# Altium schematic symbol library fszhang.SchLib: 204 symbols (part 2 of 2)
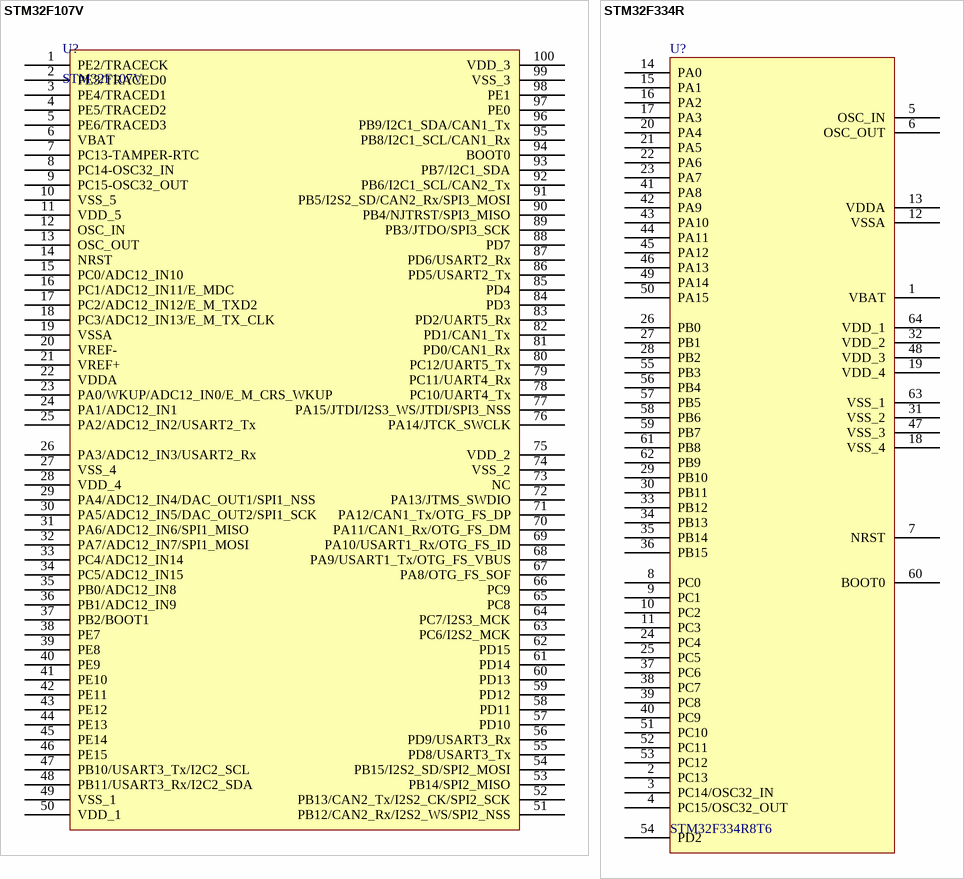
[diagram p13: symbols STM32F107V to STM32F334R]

## STM32F107V
designator U?
STM32单片机100引脚
footprint LQFP-100_M (Thin QFP, 100)
pins: 1 PE2/TRACECK, 2 PE3/TRACED0, 3 PE4/TRACED1, 4 PE5/TRACED2, 5 PE6/TRACED3, 6 VBAT, 7 PC13-TAMPER-RTC, 8 PC14-OSC32_IN, 9 PC15-OSC32_OUT, 10 VSS_5, 11 VDD_5, 12 OSC_IN, 13 OSC_OUT, 14 NRST, 15 PC0/ADC12_IN10, 16 PC1/ADC12_IN11/E_MDC, 17 PC2/ADC12_IN12/E_M_TXD2, 18 PC3/ADC12_IN13/E_M_TX_CLK, 19 VSSA, 20 VREF-, 21 VREF+, 22 VDDA, 23 PA0/WKUP/ADC12_IN0/E_M_CRS_WKUP, 24 PA1/ADC12_IN1, 25 PA2/ADC12_IN2/USART2_Tx, 26 PA3/ADC12_IN3/USART2_Rx, 27 VSS_4, 28 VDD_4, 29 PA4/ADC12_IN4/DAC_OUT1/SPI1_NSS, 30 PA5/ADC12_IN5/DAC_OUT2/SPI1_SCK, 31 PA6/ADC12_IN6/SPI1_MISO, 32 PA7/ADC12_IN7/SPI1_MOSI, 33 PC4/ADC12_IN14, 34 PC5/ADC12_IN15, 35 PB0/ADC12_IN8, 36 PB1/ADC12_IN9, 37 PB2/BOOT1, 38 PE7, 39 PE8, 40 PE9, 41 PE10, 42 PE11, 43 PE12, 44 PE13, 45 PE14, 46 PE15, 47 PB10/USART3_Tx/I2C2_SCL, 48 PB11/USART3_Rx/I2C2_SDA, 49 VSS_1, 50 VDD_1, 51 PB12/CAN2_Rx/I2S2_WS/SPI2_NSS, 52 PB13/CAN2_Tx/I2S2_CK/SPI2_SCK, 53 PB14/SPI2_MISO, 54 PB15/I2S2_SD/SPI2_MOSI, 55 PD8/USART3_Tx, 56 PD9/USART3_Rx, 57 PD10, 58 PD11, 59 PD12, 60 PD13, 61 PD14, 62 PD15, 63 PC6/I2S2_MCK, 64 PC7/I2S3_MCK, 65 PC8, 66 PC9, 67 PA8/OTG_FS_SOF, 68 PA9/USART1_Tx/OTG_FS_VBUS, 69 PA10/USART1_Rx/OTG_FS_ID, 70 PA11/CAN1_Rx/OTG_FS_DM, 71 PA12/CAN1_Tx/OTG_FS_DP, 72 PA13/JTMS_SWDIO, 73 NC, 74 VSS_2, 75 VDD_2, 76 PA14/JTCK_SWCLK, 77 PA15/JTDI/I2S3_WS/JTDI/SPI3_NSS, 78 PC10/UART4_Tx, 79 PC11/UART4_Rx, 80 PC12/UART5_Tx, 81 PD0/CAN1_Rx, 82 PD1/CAN1_Tx, 83 PD2/UART5_Rx, 84 PD3, 85 PD4, 86 PD5/USART2_Tx, 87 PD6/USART2_Rx, 88 PD7, 89 PB3/JTDO/SPI3_SCK, 90 PB4/NJTRST/SPI3_MISO, 91 PB5/I2S2_SD/CAN2_Rx/SPI3_MOSI, 92 PB6/I2C1_SCL/CAN2_Tx, 93 PB7/I2C1_SDA, 94 BOOT0, 95 PB8/I2C1_SCL/CAN1_Rx, 96 PB9/I2C1_SDA/CAN1_Tx, 97 PE0, 98 PE1, 99 VSS_3, 100 VDD_3

## STM32F334R
designator U?, comment STM32F334R8T6
STM32单片机64引脚
footprint LQFP-64_EP (LQFP64)
footprint LQFP-64 (LQFP64)
pins: 1 VBAT, 2 PC13, 3 PC14/OSC32_IN, 4 PC15/OSC32_OUT, 5 OSC_IN, 6 OSC_OUT, 7 NRST, 8 PC0, 9 PC1, 10 PC2, 11 PC3, 12 VSSA, 13 VDDA, 14 PA0, 15 PA1, 16 PA2, 17 PA3, 18 VSS_4, 19 VDD_4, 20 PA4, 21 PA5, 22 PA6, 23 PA7, 24 PC4, 25 PC5, 26 PB0, 27 PB1, 28 PB2, 29 PB10, 30 PB11, 31 VSS_2, 32 VDD_2, 33 PB12, 34 PB13, 35 PB14, 36 PB15, 37 PC6, 38 PC7, 39 PC8, 40 PC9, 41 PA8, 42 PA9, 43 PA10, 44 PA11, 45 PA12, 46 PA13, 47 VSS_3, 48 VDD_3, 49 PA14, 50 PA15, 51 PC10, 52 PC11, 53 PC12, 54 PD2, 55 PB3, 56 PB4, 57 PB5, 58 PB6, 59 PB7, 60 BOOT0, 61 PB8, 62 PB9, 63 VSS_1, 64 VDD_1

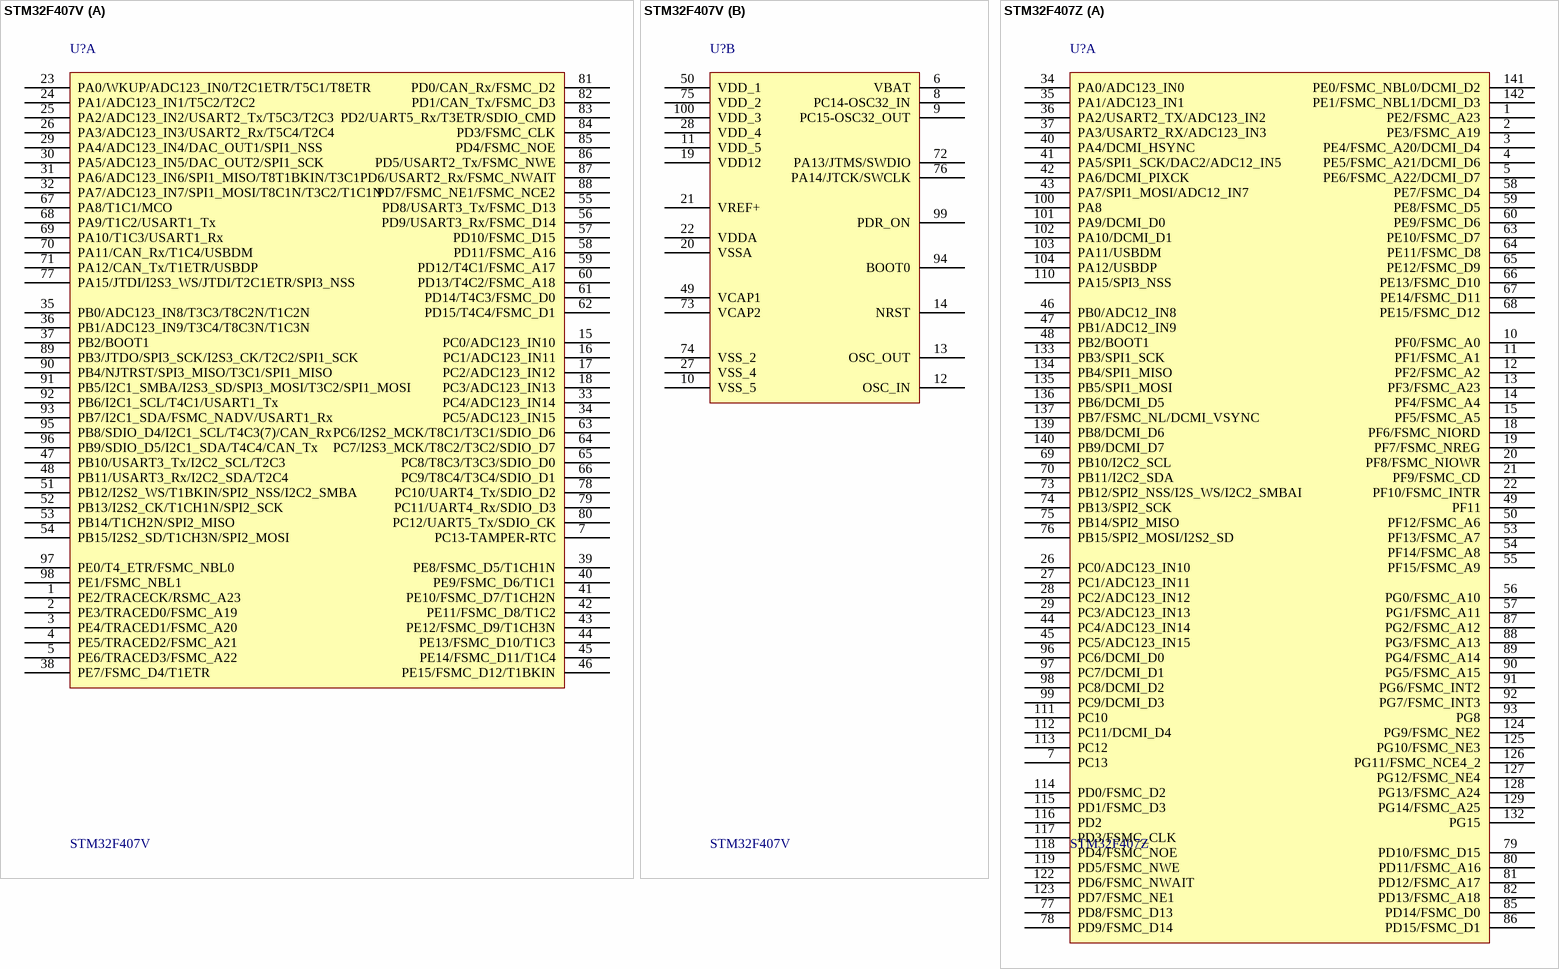
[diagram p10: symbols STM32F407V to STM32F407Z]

## STM32F407V
designator U?
STM32单片机100引脚
footprint LQFP-100_M (Thin QFP, 100)
part A pins: 1 PE2/TRACECK/RSMC_A23, 2 PE3/TRACED0/FSMC_A19, 3 PE4/TRACED1/FSMC_A20, 4 PE5/TRACED2/FSMC_A21, 5 PE6/TRACED3/FSMC_A22, 7 PC13-TAMPER-RTC, 15 PC0/ADC123_IN10, 16 PC1/ADC123_IN11, 17 PC2/ADC123_IN12, 18 PC3/ADC123_IN13, 23 PA0/WKUP/ADC123_IN0/T2C1ETR/T5C1/T8ETR, 24 PA1/ADC123_IN1/T5C2/T2C2, 25 PA2/ADC123_IN2/USART2_Tx/T5C3/T2C3, 26 PA3/ADC123_IN3/USART2_Rx/T5C4/T2C4, 29 PA4/ADC123_IN4/DAC_OUT1/SPI1_NSS, 30 PA5/ADC123_IN5/DAC_OUT2/SPI1_SCK, 31 PA6/ADC123_IN6/SPI1_MISO/T8T1BKIN/T3C1, 32 PA7/ADC123_IN7/SPI1_MOSI/T8C1N/T3C2/T1C1N, 33 PC4/ADC123_IN14, 34 PC5/ADC123_IN15, 35 PB0/ADC123_IN8/T3C3/T8C2N/T1C2N, 36 PB1/ADC123_IN9/T3C4/T8C3N/T1C3N, 37 PB2/BOOT1, 38 PE7/FSMC_D4/T1ETR, 39 PE8/FSMC_D5/T1CH1N, 40 PE9/FSMC_D6/T1C1, 41 PE10/FSMC_D7/T1CH2N, 42 PE11/FSMC_D8/T1C2, 43 PE12/FSMC_D9/T1CH3N, 44 PE13/FSMC_D10/T1C3, 45 PE14/FSMC_D11/T1C4, 46 PE15/FSMC_D12/T1BKIN, 47 PB10/USART3_Tx/I2C2_SCL/T2C3, 48 PB11/USART3_Rx/I2C2_SDA/T2C4, 51 PB12/I2S2_WS/T1BKIN/SPI2_NSS/I2C2_SMBA, 52 PB13/I2S2_CK/T1CH1N/SPI2_SCK, 53 PB14/T1CH2N/SPI2_MISO, 54 PB15/I2S2_SD/T1CH3N/SPI2_MOSI, 55 PD8/USART3_Tx/FSMC_D13, 56 PD9/USART3_Rx/FSMC_D14, 57 PD10/FSMC_D15, 58 PD11/FSMC_A16, 59 PD12/T4C1/FSMC_A17, 60 PD13/T4C2/FSMC_A18, 61 PD14/T4C3/FSMC_D0, 62 PD15/T4C4/FSMC_D1, 63 PC6/I2S2_MCK/T8C1/T3C1/SDIO_D6, 64 PC7/I2S3_MCK/T8C2/T3C2/SDIO_D7, 65 PC8/T8C3/T3C3/SDIO_D0, 66 PC9/T8C4/T3C4/SDIO_D1, 67 PA8/T1C1/MCO, 68 PA9/T1C2/USART1_Tx, 69 PA10/T1C3/USART1_Rx, 70 PA11/CAN_Rx/T1C4/USBDM, 71 PA12/CAN_Tx/T1ETR/USBDP, 77 PA15/JTDI/I2S3_WS/JTDI/T2C1ETR/SPI3_NSS, 78 PC10/UART4_Tx/SDIO_D2, 79 PC11/UART4_Rx/SDIO_D3, 80 PC12/UART5_Tx/SDIO_CK, 81 PD0/CAN_Rx/FSMC_D2, 82 PD1/CAN_Tx/FSMC_D3, 83 PD2/UART5_Rx/T3ETR/SDIO_CMD, 84 PD3/FSMC_CLK, 85 PD4/FSMC_NOE, 86 PD5/USART2_Tx/FSMC_NWE, 87 PD6/USART2_Rx/FSMC_NWAIT, 88 PD7/FSMC_NE1/FSMC_NCE2, 89 PB3/JTDO/SPI3_SCK/I2S3_CK/T2C2/SPI1_SCK, 90 PB4/NJTRST/SPI3_MISO/T3C1/SPI1_MISO, 91 PB5/I2C1_SMBA/I2S3_SD/SPI3_MOSI/T3C2/SPI1_MOSI, 92 PB6/I2C1_SCL/T4C1/USART1_Tx, 93 PB7/I2C1_SDA/FSMC_NADV/USART1_Rx, 95 PB8/SDIO_D4/I2C1_SCL/T4C3(7)/CAN_Rx, 96 PB9/SDIO_D5/I2C1_SDA/T4C4/CAN_Tx, 97 PE0/T4_ETR/FSMC_NBL0, 98 PE1/FSMC_NBL1
part B pins: 6 VBAT, 8 PC14-OSC32_IN, 9 PC15-OSC32_OUT, 10 VSS_5, 11 VDD_5, 12 OSC_IN, 13 OSC_OUT, 14 NRST, 19 VDD12, 20 VSSA, 21 VREF+, 22 VDDA, 27 VSS_4, 28 VDD_4, 49 VCAP1, 50 VDD_1, 72 PA13/JTMS/SWDIO, 73 VCAP2, 74 VSS_2, 75 VDD_2, 76 PA14/JTCK/SWCLK, 94 BOOT0, 99 PDR_ON, 100 VDD_3

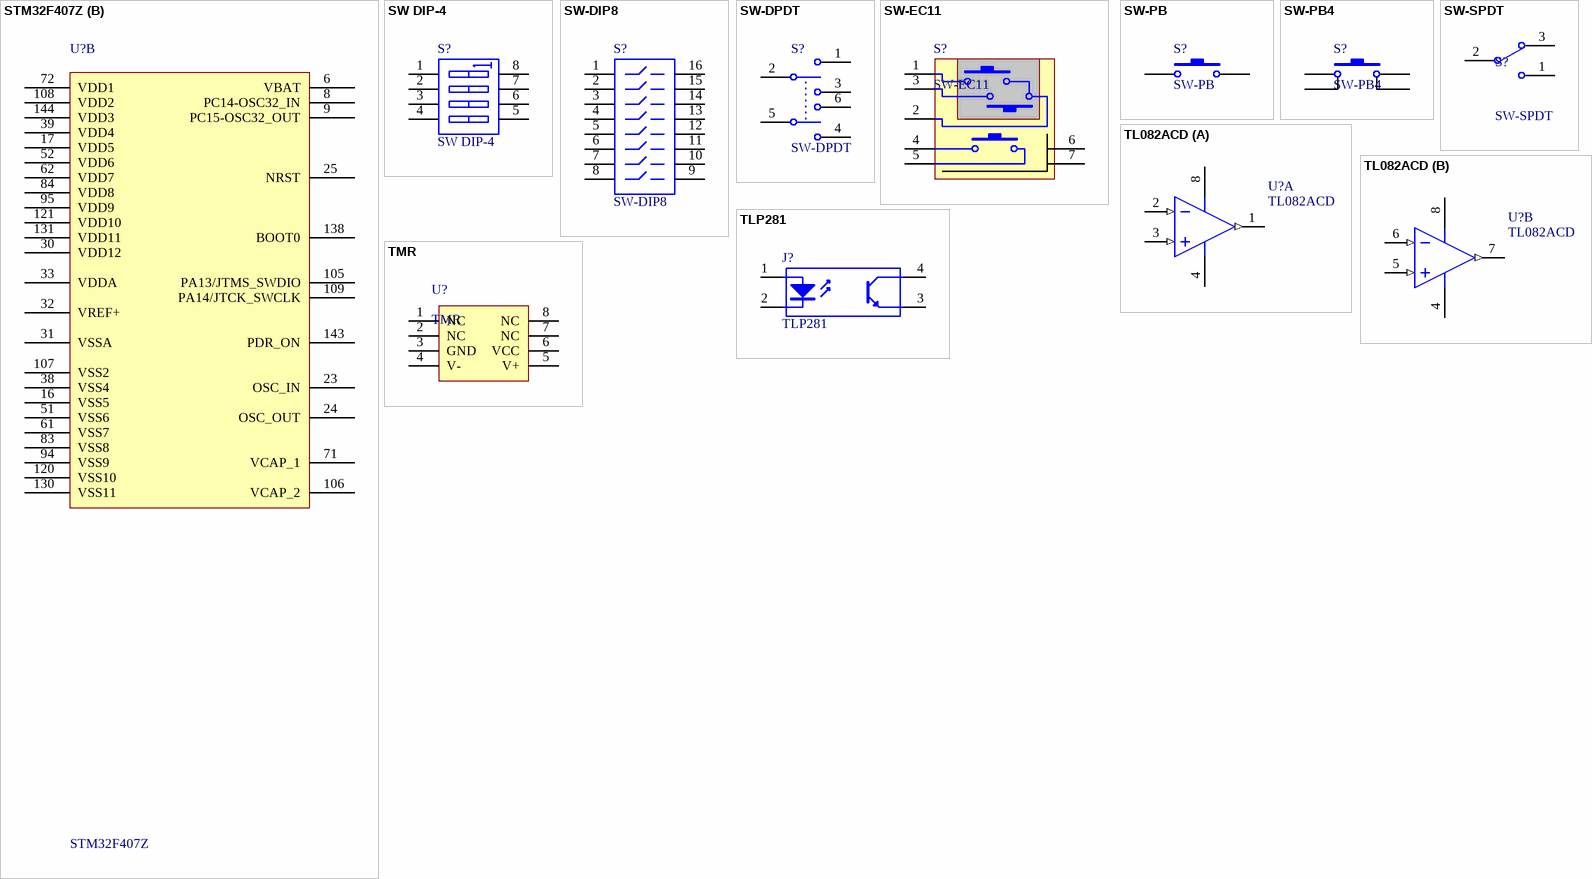
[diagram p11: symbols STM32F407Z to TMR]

## STM32F407Z
designator U?
STM32单片机144引脚
footprint TQFP144_N (TTM32V103ZET6)
part A pins: 1 PE2/FSMC_A23, 2 PE3/FSMC_A19, 3 PE4/FSMC_A20/DCMI_D4, 4 PE5/FSMC_A21/DCMI_D6, 5 PE6/FSMC_A22/DCMI_D7, 7 PC13, 10 PF0/FSMC_A0, 11 PF1/FSMC_A1, 12 PF2/FSMC_A2, 13 PF3/FSMC_A23, 14 PF4/FSMC_A4, 15 PF5/FSMC_A5, 18 PF6/FSMC_NIORD, 19 PF7/FSMC_NREG, 20 PF8/FSMC_NIOWR, 21 PF9/FSMC_CD, 22 PF10/FSMC_INTR, 26 PC0/ADC123_IN10, 27 PC1/ADC123_IN11, 28 PC2/ADC123_IN12, 29 PC3/ADC123_IN13, 34 PA0/ADC123_IN0, 35 PA1/ADC123_IN1, 36 PA2/USART2_TX/ADC123_IN2, 37 PA3/USART2_RX/ADC123_IN3, 40 PA4/DCMI_HSYNC, 41 PA5/SPI1_SCK/DAC2/ADC12_IN5, 42 PA6/DCMI_PIXCK, 43 PA7/SPI1_MOSI/ADC12_IN7, 44 PC4/ADC123_IN14, 45 PC5/ADC123_IN15, 46 PB0/ADC12_IN8, 47 PB1/ADC12_IN9, 48 PB2/BOOT1, 49 PF11, 50 PF12/FSMC_A6, 53 PF13/FSMC_A7, 54 PF14/FSMC_A8, 55 PF15/FSMC_A9, 56 PG0/FSMC_A10, 57 PG1/FSMC_A11, 58 PE7/FSMC_D4, 59 PE8/FSMC_D5, 60 PE9/FSMC_D6, 63 PE10/FSMC_D7, 64 PE11/FSMC_D8, 65 PE12/FSMC_D9, 66 PE13/FSMC_D10, 67 PE14/FSMC_D11, 68 PE15/FSMC_D12, 69 PB10/I2C2_SCL, 70 PB11/I2C2_SDA, 73 PB12/SPI2_NSS/I2S_WS/I2C2_SMBAI, 74 PB13/SPI2_SCK, 75 PB14/SPI2_MISO, 76 PB15/SPI2_MOSI/I2S2_SD, 77 PD8/FSMC_D13, 78 PD9/FSMC_D14, 79 PD10/FSMC_D15, 80 PD11/FSMC_A16, 81 PD12/FSMC_A17, 82 PD13/FSMC_A18, 85 PD14/FSMC_D0, 86 PD15/FSMC_D1, 87 PG2/FSMC_A12, 88 PG3/FSMC_A13, 89 PG4/FSMC_A14, 90 PG5/FSMC_A15, 91 PG6/FSMC_INT2, 92 PG7/FSMC_INT3, 93 PG8, 96 PC6/DCMI_D0, 97 PC7/DCMI_D1, 98 PC8/DCMI_D2, 99 PC9/DCMI_D3, 100 PA8, 101 PA9/DCMI_D0, 102 PA10/DCMI_D1, 103 PA11/USBDM, 104 PA12/USBDP, 110 PA15/SPI3_NSS, 111 PC10, 112 PC11/DCMI_D4, 113 PC12, 114 PD0/FSMC_D2, 115 PD1/FSMC_D3, 116 PD2, 117 PD3/FSMC_CLK, 118 PD4/FSMC_NOE, 119 PD5/FSMC_NWE, 122 PD6/FSMC_NWAIT, 123 PD7/FSMC_NE1, 124 PG9/FSMC_NE2, 125 PG10/FSMC_NE3, 126 PG11/FSMC_NCE4_2, 127 PG12/FSMC_NE4, 128 PG13/FSMC_A24, 129 PG14/FSMC_A25, 132 PG15, 133 PB3/SPI1_SCK, 134 PB4/SPI1_MISO, 135 PB5/SPI1_MOSI, 136 PB6/DCMI_D5, 137 PB7/FSMC_NL/DCMI_VSYNC, 139 PB8/DCMI_D6, 140 PB9/DCMI_D7, 141 PE0/FSMC_NBL0/DCMI_D2, 142 PE1/FSMC_NBL1/DCMI_D3
part B pins: 6 VBAT, 8 PC14-OSC32_IN, 9 PC15-OSC32_OUT, 16 VSS5, 17 VDD5, 23 OSC_IN, 24 OSC_OUT, 25 NRST, 30 VDD12, 31 VSSA, 32 VREF+, 33 VDDA, 38 VSS4, 39 VDD4, 51 VSS6, 52 VDD6, 61 VSS7, 62 VDD7, 71 VCAP_1, 72 VDD1, 83 VSS8, 84 VDD8, 94 VSS9, 95 VDD9, 105 PA13/JTMS_SWDIO, 106 VCAP_2, 107 VSS2, 108 VDD2, 109 PA14/JTCK_SWCLK, 120 VSS10, 121 VDD10, 130 VSS11, 131 VDD11, 138 BOOT0, 143 PDR_ON, 144 VDD3

## SW DIP-4
designator S?
编码开关
footprint SW8_4BIT (贴片)
pins: 1 A1, 2 A2, 3 A3, 4 A4, 5 B4, 6 B3, 7 B2, 8 B1

## SW-DIP8
designator S?
8位直插拨码开关
footprint DIP16-KEY (DIP拨码开关)
pins: 1, 2, 3, 4, 5, 6, 7, 8, 9, 10, 11, 12, 13, 14, 15, 16

## SW-DPDT
designator S?
单刀双掷开关
footprint SWITCH_B1 (单刀)
pins: 1, 2, 3, 4, 5, 6

## SW-EC11
designator S?
旋转编码开关
footprint EC11
pins: 1, 2, 3, 4, 5, 6, 7

## SW-PB
designator S?
微动开关
footprint SW_PB2_C1 (侧卧微动开关)
footprint SW_PB2_B1
footprint SW_PB2_A1
pins: 1, 2

## SW-PB4
designator S?
微动开关
footprint SW_PB4_A1
pins: 1, 2, 3, 4

## SW-SPDT
designator S?
开关
footprint SWITCH_A1 (Ť?)
footprint SWITCH_A2 (ƽ?)
footprint SWITCH_A3 (单刀单掷开关)
pins: 1, 2, 3

## TL082ACD
designator U?
JFET-Input Operational Amplifier
footprint NSO8_N (SOIC-max660)
pins on every part: 4 V- (power), 8 V+ (power)
part A pins: 1 OUT (out), 2 IN- (in), 3 IN+ (in)
part B pins: 5 IN+ (in), 6 IN- (in), 7 OUT (out)

## TLP281
designator J?
光耦
footprint SOP127P710X350-4N (SOP, 4-Leads, Body 2.7x4.5mm (max), Pitch 1.27mm, IPC Medium Density)
pins: 1 A "Anode", 2 K "Cathode", 3 E "Emitter", 4 C "Collector"

## TMR
designator U?
隧道磁电阻
footprint NSO8_N (SOIC-max660)
pins: 1 NC, 2 NC, 3 GND, 4 V-, 5 V+, 6 VCC, 7 NC, 8 NC

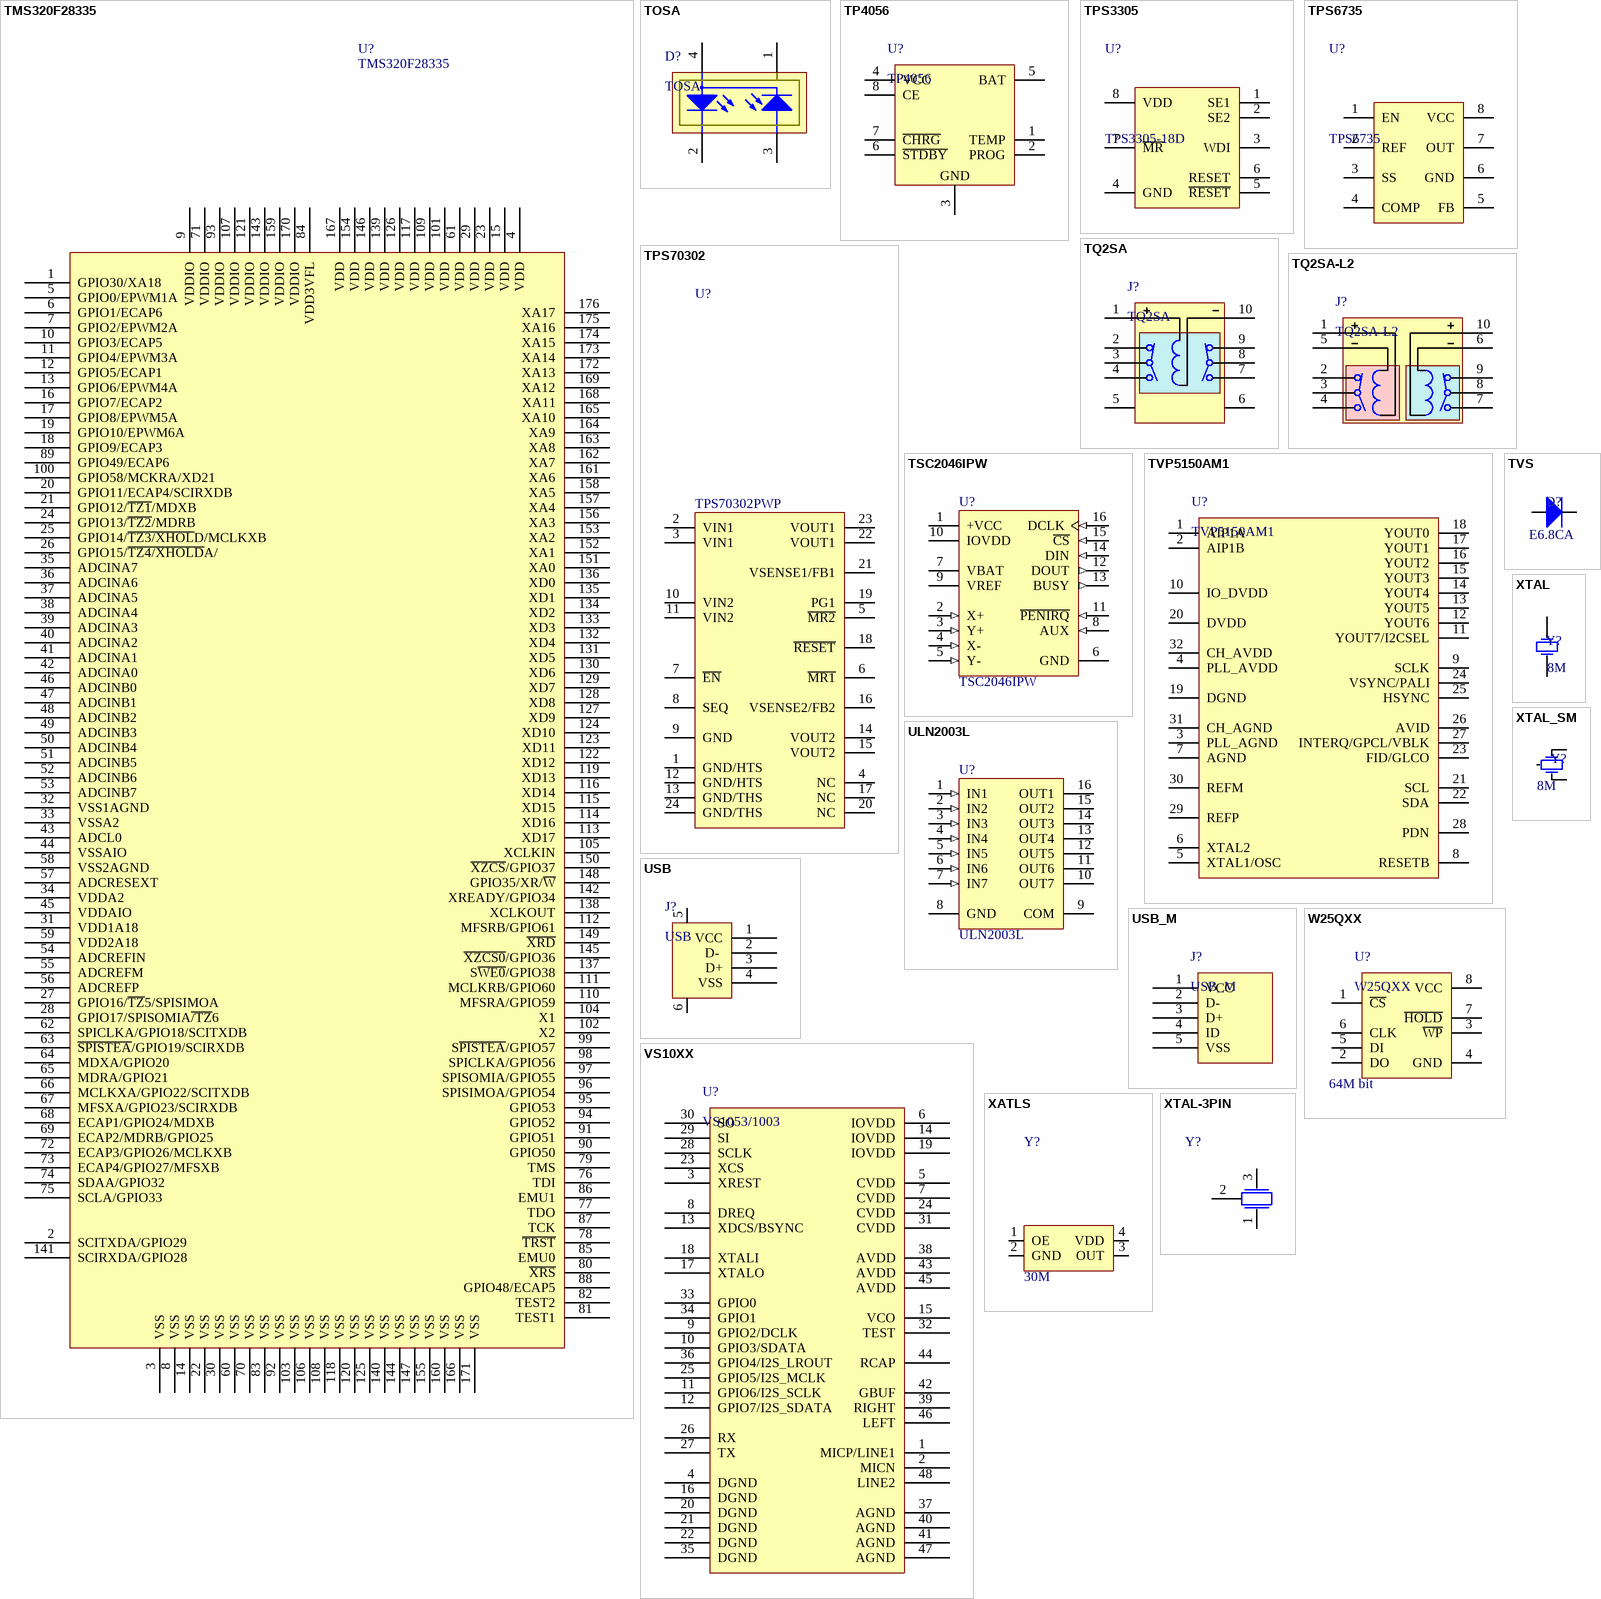
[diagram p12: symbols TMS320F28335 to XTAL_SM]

## TMS320F28335
designator U?
DSPоƬ
footprint LQFP-176_M (Thin QFP, 176-Leads, Body 24x24mm, Pitch 0.5mm, IPC Low Density)
pins: 1 GPIO30/XA18, 2 SCITXDA/GPIO29, 3 VSS, 4 VDD, 5 GPIO0/EPWM1A, 6 GPIO1/ECAP6, 7 GPIO2/EPWM2A, 8 VSS, 9 VDDIO, 10 GPIO3/ECAP5, 11 GPIO4/EPWM3A, 12 GPIO5/ECAP1, 13 GPIO6/EPWM4A, 14 VSS, 15 VDD, 16 GPIO7/ECAP2, 17 GPIO8/EPWM5A, 18 GPIO9/ECAP3, 19 GPIO10/EPWM6A, 20 GPIO11/ECAP4/SCIRXDB, 21 GPIO12/~{TZ1}/MDXB, 22 VSS, 23 VDD, 24 GPIO13/~{TZ2}/MDRB, 25 GPIO14/~{TZ3/XHOL}D/MCLKXB, 26 GPIO15/~{TZ4/XHOLD}A/, 27 GPIO16/~{TZ}5/SPISIMOA, 28 GPIO17/SPISOMIA~{/TZ}6, 29 VDD, 30 VSS, 31 VDD1A18, 32 VSS1AGND, 33 VSSA2, 34 VDDA2, 35 ADCINA7, 36 ADCINA6, 37 ADCINA5, 38 ADCINA4, 39 ADCINA3, 40 ADCINA2, 41 ADCINA1, 42 ADCINA0, 43 ADCL0, 44 VSSAIO, 45 VDDAIO, 46 ADCINB0, 47 ADCINB1, 48 ADCINB2, 49 ADCINB3, 50 ADCINB4, 51 ADCINB5, 52 ADCINB6, 53 ADCINB7, 54 ADCREFIN, 55 ADCREFM, 56 ADCREFP, 57 ADCRESEXT, 58 VSS2AGND, 59 VDD2A18, 60 VSS, 61 VDD, 62 SPICLKA/GPIO18/SCITXDB, 63 ~{SPISTEA}/GPIO19/SCIRXDB, 64 MDXA/GPIO20, 65 MDRA/GPIO21, 66 MCLKXA/GPIO22/SCITXDB, 67 MFSXA/GPIO23/SCIRXDB, 68 ECAP1/GPIO24/MDXB, 69 ECAP2/MDRB/GPIO25, 70 VSS, 71 VDDIO, 72 ECAP3/GPIO26/MCLKXB, 73 ECAP4/GPIO27/MFSXB, 74 SDAA/GPIO32, 75 SCLA/GPIO33, 76 TDI, 77 TDO, 78 ~{TRST}, 79 TMS, 80 ~{XRS}, 81 TEST1, 82 TEST2, 83 VSS, 84 VDD3VFL, 85 EMU0, 86 EMU1, 87 TCK, 88 GPIO48/ECAP5, 89 GPIO49/ECAP6, 90 GPIO50, 91 GPIO51, 92 VSS, 93 VDDIO, 94 GPIO52, 95 GPIO53, 96 SPISIMOA/GPIO54, 97 SPISOMIA/GPIO55, 98 SPICLKA/GPIO56, 99 S~{PISTEA}/GPIO57, 100 GPIO58/MCKRA/XD21, 101 VDD, 102 X2, 103 VSS, 104 X1, 105 XCLKIN, 106 VSS, 107 VDDIO, 108 VSS, 109 VDD, 110 MFSRA/GPIO59, 111 MCLKRB/GPIO60, 112 MFSRB/GPIO61, 113 XD17, 114 XD16, 115 XD15, 116 XD14, 117 VDD, 118 VSS, 119 XD13, 120 VSS, 121 VDDIO, 122 XD12, 123 XD11, 124 XD10, 125 VSS, 126 VDD, 127 XD9, 128 XD8, 129 XD7, 130 XD6, 131 XD5, 132 XD4, 133 XD3, 134 XD2, 135 XD1, 136 XD0, 137 S~{WE0}/GPIO38, 138 XCLKOUT, 139 VDD, 140 VSS, 141 SCIRXDA/GPIO28, 142 XREADY/GPIO34, 143 VDDIO, 144 VSS, 145 ~{XZCS0}/GPIO36, 146 VDD, 147 VSS, 148 GPIO35/XR/~{W}, 149 ~{XRD}, 150 ~{XZCS}/GPIO37, 151 XA0, 152 XA1, 153 XA2, 154 VDD, 155 VSS, 156 XA3, 157 XA4, 158 XA5, 159 VDDIO, 160 VSS, 161 XA6, 162 XA7, 163 XA8, 164 XA9, 165 XA10, 166 VSS, 167 VDD, 168 XA11, 169 XA12, 170 VDDIO, 171 VSS, 172 XA13, 173 XA14, 174 XA15, 175 XA16, 176 XA17

## TOSA
designator D?
激光器
footprint LD-4P
pins: 1 GND, 2 LD-, 3 PD, 4 PW

## TP4056
designator U?
锂电池充电管理
footprint NSO8_TP4056 (SOIC-max660)
pins: 1 TEMP, 2 PROG, 3 GND, 4 VCC, 5 BAT, 6 ~{STDBY}, 7 ~{CHRG}, 8 CE

## TPS3305
designator U?, comment TPS3305-18D
DSP电源管理
footprint TSSOP-8
pins: 1 SE1, 2 SE2, 3 WDI, 4 GND, 5 ~{RESET}, 6 RESET, 7 ~{MR}, 8 VDD

## TPS6735
designator U?
负电压芯片
footprint NSO8_N (SOIC-max660)
pins: 1 EN, 2 REF, 3 SS, 4 COMP, 5 FB, 6 GND, 7 OUT, 8 VCC

## TPS70302
designator U?, comment TPS70302PWP
DSP电源芯片
footprint TSSOP24P (Shrink Small Outline; 24 Leads; Body Width 4.4 mm; Pitch 0.65 mm)
pins: 1 GND/HTS, 2 VIN1, 3 VIN1, 4 NC, 5 ~{MR2}, 6 ~{MR1}, 7 ~{EN}, 8 SEQ, 9 GND, 10 VIN2, 11 VIN2, 12 GND/HTS, 13 GND/THS, 14 VOUT2, 15 VOUT2, 16 VSENSE2/FB2, 17 NC, 18 ~{RESET}, 19 PG1, 20 NC, 21 VSENSE1/FB1, 22 VOUT1, 23 VOUT1, 24 GND/THS

## TQ2SA
designator J?
单通道继电器
footprint SOP254P1150X560-10N (双继电器10PIN)
pins: 1, 2, 3, 4, 5, 6, 7, 8, 9, 10

## TQ2SA-L2
designator J?
双通道双稳态继电器
footprint SOP254P1150X560-10N (双继电器10PIN)
pins: 1, 2, 3, 4, 5, 6, 7, 8, 9, 10

## TSC2046IPW
designator U?
触摸驱动芯片
footprint PW016 (Shrink Small Outline; 16 Leads; Body Width 4.4 mm; Pitch 0.65 mm)
pins: 1 +VCC (power), 2 X+ (in), 3 Y+ (in), 4 X- (in), 5 Y- (in), 6 GND (power), 7 VBAT (power), 8 AUX (in), 9 VREF (power), 10 IOVDD (power), 11 ~{PENIRQ} (in), 12 DOUT (out), 13 BUSY (out), 14 DIN (in), 15 ~{CS} (in), 16 DCLK (in)

## TVP5150AM1
designator U?
视频解码芯片
footprint TQFP-32
pins: 1 AIP1A, 2 AIP1B, 3 PLL_AGND, 4 PLL_AVDD, 5 XTAL1/OSC, 6 XTAL2, 7 AGND, 8 RESETB, 9 SCLK, 10 IO_DVDD, 11 YOUT7/I2CSEL, 12 YOUT6, 13 YOUT5, 14 YOUT4, 15 YOUT3, 16 YOUT2, 17 YOUT1, 18 YOUT0, 19 DGND, 20 DVDD, 21 SCL, 22 SDA, 23 FID/GLCO, 24 VSYNC/PALI, 25 HSYNC, 26 AVID, 27 INTERQ/GPCL/VBLK, 28 PDN, 29 REFP, 30 REFM, 31 CH_AGND, 32 CH_AVDD

## TVS
designator D?  Type: E6.8CA  (hidden comment: TVS)
TVS保护
footprint DIODE-AXL (直插二极管)
footprint DIODE-1206 (玻璃封装二极管)
footprint DIODE-SMA (贴片二极管)
footprint DIODE-SMB (DO-214-AA/SMB; 2 C-Bend Leads; Body 5.3 x 3.6 mm, inc. leads (LxW))
pins: 1 A, 2 K

## ULN2003L
designator U?
驱动芯片
footprint NSO16_M (SOIC, 16-Leads, Body 9.9x3.9mm, Pitch 1.27mm, IPC Low Density)
pins: 1 IN1 (in), 2 IN2 (in), 3 IN3 (in), 4 IN4 (in), 5 IN5 (in), 6 IN6 (in), 7 IN7 (in), 8 GND (power), 9 COM, 10 OUT7 (oc), 11 OUT6 (oc), 12 OUT5 (oc), 13 OUT4 (oc), 14 OUT3 (oc), 15 OUT2 (oc), 16 OUT1 (oc)

## USB
designator J?
USB接口
footprint USB_B1 (USB方?)
footprint USB_A1
footprint USB_C1 (侧卧USB)
pins: 1 VCC, 2 D- , 3 D+, 4 VSS, 5, 6

## USB_M
designator J?
MicroUSB接口
footprint USB_MICRO (USB方孔)
pins: 1 VCC, 2 D- , 3 D+, 4 ID, 5 VSS

## VS10XX
designator U?, comment VS1053/1003
音频解码芯片
footprint LQFP-48_M (Thin QFP, 48-Leads, Body 7x7mm, Pitch 0.5mm, IPC Low Density)
pins: 1 MICP/LINE1, 2 MICN, 3 XREST, 4 DGND, 5 CVDD, 6 IOVDD, 7 CVDD, 8 DREQ, 9 GPIO2/DCLK, 10 GPIO3/SDATA, 11 GPIO6/I2S_SCLK, 12 GPIO7/I2S_SDATA, 13 XDCS/BSYNC, 14 IOVDD, 15 VCO, 16 DGND, 17 XTALO, 18 XTALI, 19 IOVDD, 20 DGND, 21 DGND, 22 DGND, 23 XCS, 24 CVDD, 25 GPIO5/I2S_MCLK, 26 RX, 27 TX, 28 SCLK, 29 SI, 30 SO, 31 CVDD, 32 TEST, 33 GPIO0, 34 GPIO1, 35 DGND, 36 GPIO4/I2S_LROUT, 37 AGND, 38 AVDD, 39 RIGHT, 40 AGND, 41 AGND, 42 GBUF, 43 AVDD, 44 RCAP, 45 AVDD, 46 LEFT, 47 AGND, 48 LINE2

## W25QXX
designator U?  Memory: 64M bit
SPI FLASH
footprint SOIC8_W (SPI_FLASH)
pins: 1 ~{CS}, 2 DO, 3 ~{WP}, 4 GND, 5 DI, 6 CLK, 7 ~{HOLD}, 8 VCC

## XATLS
designator Y?  value 30M  (hidden comment: XATLS)
贴片有源晶振
footprint X-CPX75
pins: 1 OE, 2 GND, 3 OUT, 4 VDD

## XTAL
designator Y?  value 8M  (hidden comment: XTAL)
晶振
footprint X-HC49U (插件晶振)
footprint X-SM49
footprint X-5032
pins: 1 OSC1, 2 OSC2

## XTAL-3PIN
designator Y?  (value not drawn)
贴片晶振
footprint X-CPX20 (贴片晶振)
pins: 1, 2, 3

## XTAL_SM
designator Y?  value 8M  (hidden comment: XTAL_SM)
圆柱晶振
footprint X-TC15 (圆柱晶振1)
footprint X-TC26 (圆柱晶振2)
pins: 1 OSC1, 2 OSC2, 3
